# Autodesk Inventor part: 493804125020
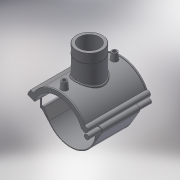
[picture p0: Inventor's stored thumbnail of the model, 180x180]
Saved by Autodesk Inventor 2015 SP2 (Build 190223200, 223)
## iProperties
Created: 2017-07
Part Number: 493804125020
Material: Generic
Description: PLASSON TRANSITION SADDLE 125-2"
Document SubType Name: Modeling
Designer: KIM
Density: 1 g/cm^3
Appearance: Default
Author: KIM
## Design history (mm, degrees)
derived "493804.ipt"
feature "Solid1::493804.ipt"
tag "TaggingFeature1"
body "Solid1"
other parameters: "d0" = 125, "d1" = 143.75, "d2" = 166, "d3" = 31.25, "d4" = 176, "d5" = 0, "d6" = 0.1, "d8" = 0, "d19" = 6, "d20" = 6, "d21" = 105.6, "d23" = 0, "d24" = 52.8, "d26" = 0, "d27" = 3, "d28" = 3, "d29" = 3, "d30" = 41.66667, "d31" = 6, "d32" = 0, "d33" = 0, "d34" = 0.6, "d40" = 74.75, "d41" = 79.3184, "d43" = 0, "d45" = 0, "d47" = 147.875, "d48" = 73.6528, "d50" = 0, "d70" = 15, "d72" = 0, "d73" = 6, "d75" = 5, "d76" = 0, "d77" = 6.25, "d78" = 92.5, "d79" = 15, "d80" = 70.4, "d82" = 5 deg, "d84" = 4, "d85" = 14, "d86" = 0, "d87" = 3, "d88" = 0, "d89" = 1, "d90" = 1, "d91" = 140.8, "d92" = 0, "d93" = 0.5, "d94" = 65.78947, "d96" = 146.625, "d97" = 3.52, "d98" = 0, "d102" = 1.69968, "d103" = 56.656, "d104" = 45.6, "d105" = 0, "d106" = 45.3248, "d108" = 0, "d109" = -25.33333, "d111" = 0.5, "d112" = 0.5, "d113" = 0, "d114" = 0.5, "d117" = 0.56656, "d120" = 140 deg, "d121" = 24.228, "d122" = 20 deg, "d123" = 287.5, "d124" = 86.25, "d126" = 0, "d143" = 128.75, "d145" = 14.42308, "d149" = 1.875, "d150" = 15.86538, "d153" = 176, "d154" = 0, "d156" = 71.875, "d157" = 160 deg, "d159" = 3.75, "d161" = 1.875, "d162" = 105.6, "d163" = 0, "d164" = 62.5, "d167" = 12.5, "d168" = 70.12195, "d170" = 1.875, "d172" = 0, "d173" = 1, "d175" = 62.5, "d176" = 20 deg, "d177" = 8.75, "d178" = 18.75, "d180" = 0, "d183" = 7.5, "d184" = 7, "d185" = 57.2, "d186" = 57.2, "d187" = 71.875, "d188" = 5.625, "d189" = 8.75, "d190" = 0, "d191" = 86.25, "d193" = 3.75, "d194" = 4.4, "d195" = 90 deg, "d197" = 0, "d199" = 0, "d_" = 125, "B_" = 166, "H_" = 76, "L_" = 176, "d_t" = 6, "G_" = 56.656, "d148" = 1.875, "d160" = 1.875, "d169" = 1.875, "d192" = 3.75
